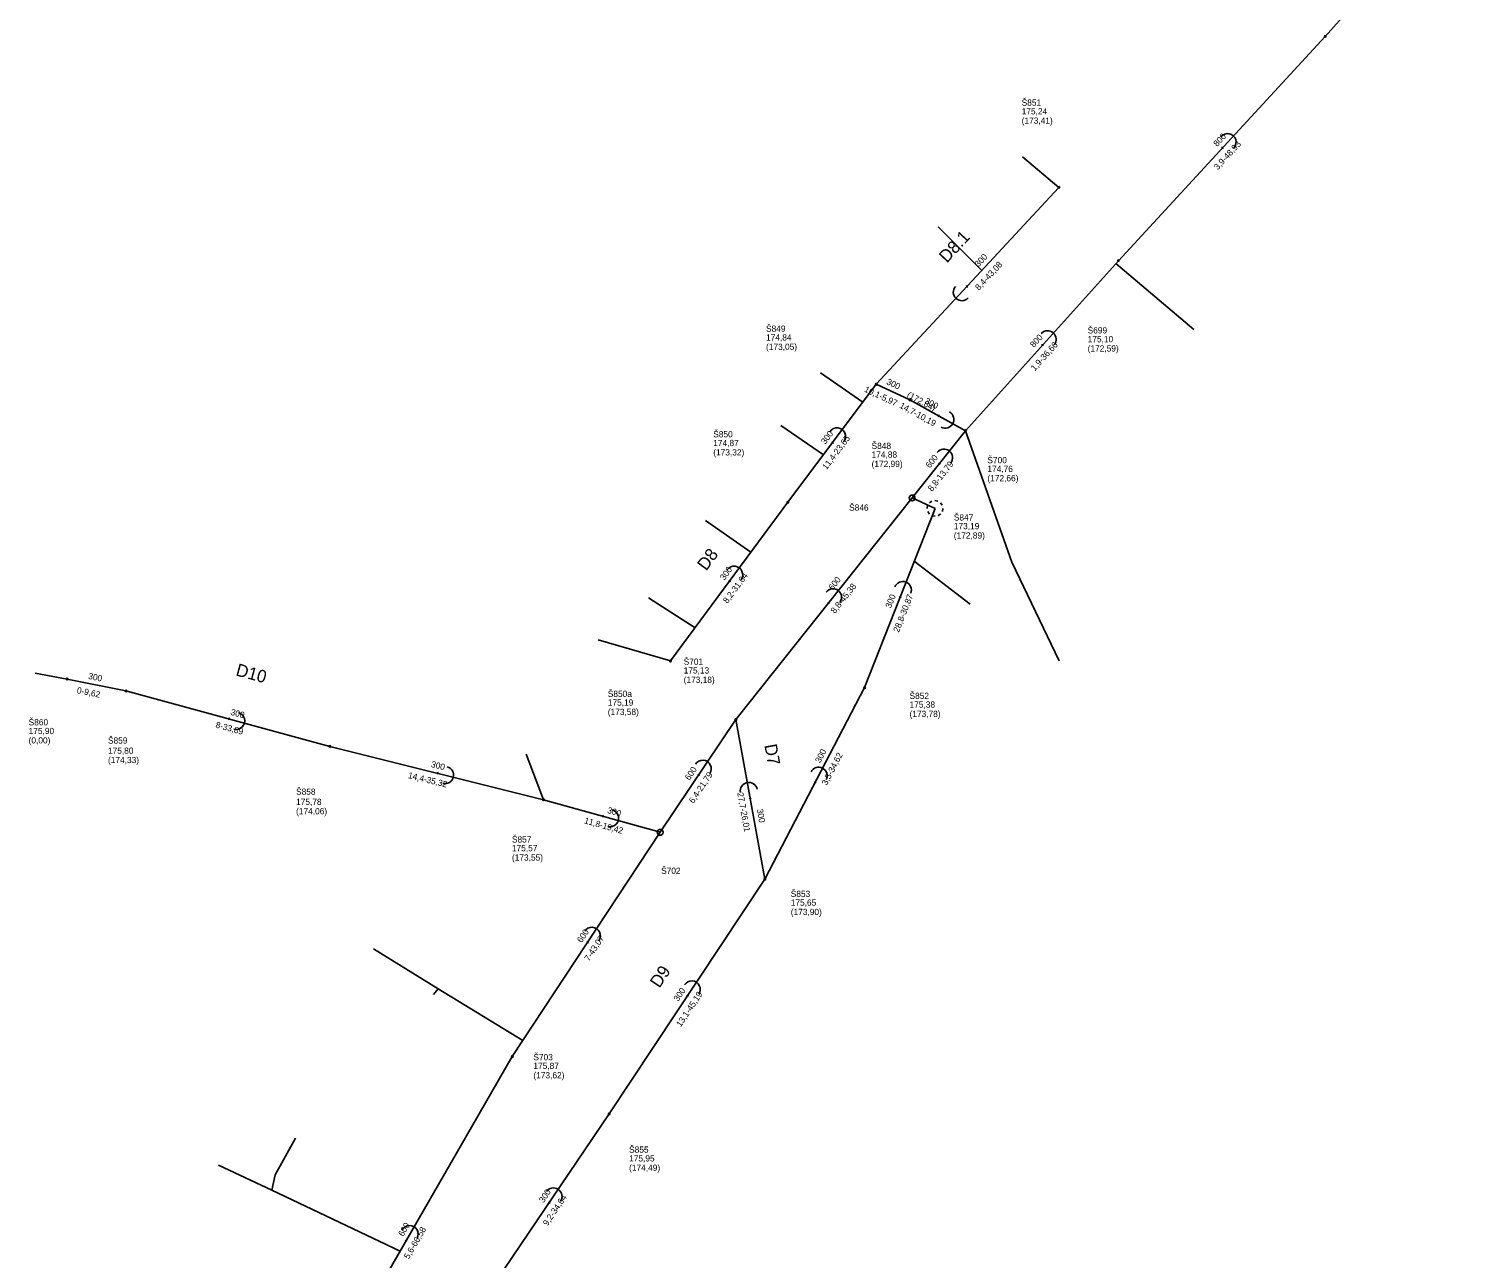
# Model space of a CAD drawing. Extents: x -548529 to -543591, y -1201432 to -1192608.
# Drawn here: x -545629 to -545396.5, y -1194134.3 to -1193937.1 of the extents above; entities that cross this region are included whole.
import ezdxf

# ---------------------------------------------------------------- set-up
doc = ezdxf.new("R2010")
doc.units = 0
for name, color, linetype in [('C3D_Bod-Značky', 7, 'Continuous'), ('C3D_Koridor', 7, 'Continuous'), ('C3D_Křižovatka', 7, 'Continuous'), ('C3D_Netisknutelná', 7, 'Continuous'), ('C3D_PP-zobrazeni v PR', 7, 'Continuous'), ('C3D_PR-Popisek', 7, 'Continuous'), ('C3D_SPR-Popisek', 7, 'Continuous'), ('C3D_Tlakove_potrubi_Popis', 7, 'Continuous'), ('C3D_ZPR-Formaty', 7, 'Continuous')]:
    doc.layers.add(name, color=color, linetype=linetype)

# ---------------------------------------------------------------- blocks, each defined once
blk = doc.blocks.new('100')
at = {"layer": 'Defpoints'}
blk.add_circle((0, 0), 0.127, dxfattribs=at)
blk = doc.blocks.new('101')
at = {"layer": 'Defpoints'}
blk.add_circle((0, 0), 0.463, dxfattribs=at)
blk = doc.blocks.new('102')
at = {"layer": 'Defpoints'}
for p, q in [((-1.17, -0.49), (-1.27, 0)), ((-1.17, 0.49), (-0.9, 0.9)), ((-0.49, 1.17), (0, 1.27)), ((0.49, 1.17), (0.9, 0.9)), ((1.17, 0.49), (1.27, 0)), ((-0.49, -1.17), (-0.9, -0.9)), ((0.49, -1.17), (0, -1.27)), ((1.17, -0.49), (0.9, -0.9))]:
    blk.add_line(p, q, dxfattribs=at)
blk = doc.blocks.new('86')
at = {"layer": 'Defpoints'}
blk.add_lwpolyline([(0.08, 0.14), (0.19, 0), (0.08, -0.14)], dxfattribs=at)
blk.add_arc((1.37, 0), 1.37, 270, 90, dxfattribs=at)
blk = doc.blocks.new('91')
at = {"layer": 'Defpoints'}
blk.add_lwpolyline([(0.08, 0.14), (0.19, 0), (0.08, -0.14)], dxfattribs=at)
blk.add_arc((1.37, 0), 1.37, 270, 90, dxfattribs=at)

msp = doc.modelspace()

# ---------------------------------------------------------------- linework, layer by layer
at = {"layer": 'C3D_Bod-Značky'}
for points in [[(-545421.142, -1193938.256), (-545396.484, -1193910.624)], [(-545454.318, -1193974.219), (-545421.142, -1193938.256)], [(-545463.86, -1193962.46), (-545493.163, -1193994.034)], [(-545478.832, -1194001.476), (-545454.318, -1193974.219)], [(-545507.34, -1194012.96), (-545493.163, -1193994.034)], [(-545493.163, -1193994.034), (-545487.754, -1193996.557)], [(-545487.754, -1193996.557), (-545478.832, -1194001.476)], [(-545487.415, -1194012.27), (-545478.832, -1194001.476)], [(-545526.15, -1194038.4), (-545507.34, -1194012.96)], [(-545515.662, -1194047.793), (-545487.415, -1194012.27)], [(-545495.027, -1194042.672), (-545483.733, -1194013.942)], [(-545483.733, -1194013.942), (-545487.415, -1194012.27)], [(-545622.922, -1194041.307), (-545613.493, -1194043.214)], [(-545613.493, -1194043.214), (-545580.788, -1194052.09)], [(-545511.007, -1194073.384), (-545495.027, -1194042.672)], [(-545527.812, -1194065.877), (-545515.662, -1194047.793)], [(-545511.007, -1194073.384), (-545515.662, -1194047.793)], [(-545580.788, -1194052.09), (-545546.515, -1194060.642)], [(-545546.515, -1194060.642), (-545527.812, -1194065.877)], [(-545551.526, -1194101.831), (-545527.812, -1194065.877)], [(-545535.994, -1194111.041), (-545511.007, -1194073.384)], [(-545584.807, -1194159.503), (-545569.894, -1194133.66), (-545551.526, -1194101.831)], [(-545555.391, -1194139.74), (-545535.994, -1194111.041)]]:
    msp.add_lwpolyline(points, dxfattribs=at)
at = {"layer": 'C3D_Koridor'}
for points in [[(-545463.86, -1193962.46), (-545469.711, -1193957.58)], [(-545476.245, -1193975.805), (-545483.202, -1193968.8)], [(-545454.706, -1193974.65), (-545442.238, -1193985.272)], [(-545495.305, -1193996.893), (-545502.079, -1193992.182)], [(-545501.629, -1194005.336), (-545508.485, -1194000.645)], [(-545478.832, -1194001.476), (-545471.428, -1194022.539), (-545463.838, -1194038.386)], [(-545513.272, -1194020.983), (-545520.525, -1194015.877)], [(-545487.048, -1194022.374), (-545478.091, -1194029.296)], [(-545522.208, -1194033.069), (-545529.702, -1194028.278)], [(-545526.15, -1194038.4), (-545537.781, -1194035.009)], [(-545622.922, -1194041.307), (-545628.047, -1194040.355)], [(-545546.515, -1194060.642), (-545549.299, -1194053.365)], [(-545549.841, -1194099.277), (-545563.417, -1194090.957), (-545573.785, -1194084.563)], [(-545563.417, -1194090.957), (-545564.157, -1194091.896)], [(-545590.088, -1194123.245), (-545589.572, -1194120.8), (-545586.282, -1194114.925)], [(-545569.529, -1194133.028), (-545590.088, -1194123.245), (-545598.657, -1194119.235)]]:
    msp.add_lwpolyline(points, dxfattribs=at)

# ---------------------------------------------------------------- block references
at = {"layer": 'C3D_PP-zobrazeni v PR'}
for name, p, xscale, yscale, rotation in [('100', (-545421.142, -1193938.256), 1.0000000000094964, 1.0000000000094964, -132.0000013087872), ('100', (-545463.86, -1193962.46), 1.0000000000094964, 1.0000000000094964, 47.99999869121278), ('100', (-545454.318, -1193974.219), 1.0000000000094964, 1.0000000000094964, -132.0000013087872), ('100', (-545493.163, -1193994.034), 1.000000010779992, 1.0000000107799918, -128.99999891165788), ('100', (-545487.754, -1193996.557), 1.0138865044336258, 1.0138865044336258, 152.43468640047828), ('100', (-545478.832, -1194001.476), 0.9999999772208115, 0.9999999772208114, 100.00000028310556), ('101', (-545487.415, -1194012.27), 1.000000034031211, 1.0000000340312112, -128.00000040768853), ('100', (-545507.34, -1194012.96), 1.000000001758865, 1.000000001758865, -125.99999933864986), ('102', (-545483.733, -1194013.942), 1.0000000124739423, 1.000000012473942, -67.0000004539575), ('100', (-545526.15, -1194038.4), 1.000000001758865, 1.000000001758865, -125.99999933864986), ('100', (-545622.922, -1194041.307), 1.0060666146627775, 1.0060666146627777, 167.3452647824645), ('100', (-545613.493, -1194043.214), 1.0028916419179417, 1.0028916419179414, 166.30279126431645), ('100', (-545495.027, -1194042.672), 0.9999999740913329, 0.9999999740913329, 65.99999939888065), ('100', (-545515.662, -1194047.793), 1.0000000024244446, 1.0000000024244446, 75.99999967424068), ('100', (-545580.788, -1194052.09), 1.0009848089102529, 1.000984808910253, 165.77567372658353), ('100', (-545546.515, -1194060.642), 1.0009848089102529, 1.000984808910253, 165.77567372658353), ('101', (-545527.812, -1194065.877), 1.0275072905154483, 1.027507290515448, -155.31089431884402), ('100', (-545511.007, -1194073.384), 0.9999999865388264, 0.9999999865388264, 59.99999955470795), ('100', (-545551.526, -1194101.831), 1.0000000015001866, 1.0000000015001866, -120.99999982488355), ('100', (-545535.994, -1194111.041), 0.9999999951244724, 0.9999999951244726, 56.999998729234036)]:
    msp.add_blockref(name, p, dxfattribs=dict(at, xscale=xscale, yscale=yscale, rotation=rotation))
at = {"layer": 'C3D_SPR-Popisek'}
for name, p, xscale, yscale, rotation in [('91', (-545437.73, -1193956.238), 1.0000000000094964, 1.0000000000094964, 47.99999869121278), ('91', (-545478.512, -1193978.247), 1.0000000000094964, 1.0000000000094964, -132.0000013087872), ('91', (-545466.575, -1193987.848), 1.0000000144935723, 1.0000000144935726, 49.00000089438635), ('91', (-545483.293, -1193999.016), 1.0072562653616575, 1.0072562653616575, -28.76666512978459), ('91', (-545500.252, -1194003.497), 1.000000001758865, 1.000000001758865, 54.00000066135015), ('91', (-545483.124, -1194006.873), 1.000000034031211, 1.0000000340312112, 51.999999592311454), ('91', (-545516.745, -1194025.68), 1.000000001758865, 1.000000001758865, 54.00000066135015), ('86', (-545489.38, -1194028.307), 0.9999999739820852, 0.9999999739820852, 68.99999941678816), ('91', (-545500.936, -1194029.274), 1.000000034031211, 1.0000000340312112, 51.999999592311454), ('86', (-545597.14, -1194047.652), 0.999999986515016, 0.9999999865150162, -15.000000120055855), ('86', (-545563.651, -1194056.366), 1.0009848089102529, 1.000984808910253, -14.224326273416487), ('91', (-545521.737, -1194056.835), 0.9999999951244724, 0.9999999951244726, 56.999998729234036), ('86', (-545503.017, -1194058.028), 0.9999999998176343, 0.9999999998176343, 63.00000066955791), ('86', (-545513.334, -1194060.588), 0.999999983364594, 0.9999999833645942, 101.0000002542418), ('86', (-545537.163, -1194063.26), 0.999999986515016, 0.9999999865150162, -15.000000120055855), ('91', (-545539.516, -1194083.622), 0.9999999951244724, 0.9999999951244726, 56.999998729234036), ('86', (-545523.5, -1194092.212), 0.9999999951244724, 0.9999999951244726, 56.999998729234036), ('86', (-545545.692, -1194125.39), 0.9999999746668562, 0.999999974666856, 55.999999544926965), ('91', (-545568.647, -1194131.5), 1.0000000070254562, 1.0000000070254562, 61.000001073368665)]:
    msp.add_blockref(name, p, dxfattribs=dict(at, xscale=xscale, yscale=yscale, rotation=rotation))

# ---------------------------------------------------------------- texts
at = {"layer": 'C3D_Křižovatka'}
for s, p in [('Š851', (-545469.83, -1193949.37)), ('Š849', (-545510.833, -1193985.624)), ('Š699', (-545459.248, -1193985.889)), ('Š850', (-545519.3, -1194002.55)), ('Š848', (-545493.904, -1194004.407)), ('Š700', (-545475.332, -1194006.696)), ('Š846', (-545497.505, -1194014.31)), ('Š847', (-545480.713, -1194015.882)), ('Š701', (-545524.042, -1194039.013)), ('Š850a', (-545536.21, -1194044.17)), ('Š852', (-545487.817, -1194044.492)), ('Š860', (-545629.102, -1194048.727)), ('Š859', (-545616.373, -1194051.654)), ('Š858', (-545586.208, -1194059.86)), ('Š857', (-545551.585, -1194067.512)), ('Š702', (-545527.662, -1194072.537)), ('Š853', (-545506.867, -1194076.244)), ('Š703', (-545548.146, -1194102.431)), ('Š855', (-545532.794, -1194117.251))]:
    msp.add_text(s, height=1, dxfattribs=at).set_placement(p)
at = {"layer": 'C3D_Netisknutelná'}
for s, rotation, p in [('D8.1', 47.14, (-545481.823, -1193974.686)), ('D8', 53.52, (-545520.426, -1194024.058)), ('D10', 344.82, (-545595.991, -1194040.702)), ('D7', 280.31, (-545511.11, -1194051.897)), ('D9', 56.43, (-545527.932, -1194090.961))]:
    msp.add_text(s, height=2, rotation=rotation, dxfattribs=at).set_placement(p)
at = {"layer": 'C3D_PR-Popisek'}
for s, rotation, p in [('800', 47.31, (-545438.47, -1193956.004)), ('300', 47.14, (-545476.744, -1193975.311)), ('800', 48.03, (-545467.859, -1193988.235)), ('300', 334.99, (-545491.617, -1193993.987)), ('300', 331.13, (-545485.51, -1193996.993)), ('300', 53.16, (-545501.315, -1194003.75)), ('600', 51.51, (-545484.566, -1194007.564)), ('300', 53.52, (-545517.514, -1194025.544)), ('600', 51.51, (-545500.135, -1194027.144)), ('300', 68.54, (-545490.81, -1194030.022)), ('300', 348.57, (-545619.599, -1194041.265)), ('300', 344.82, (-545596.788, -1194047.025)), ('300', 62.51, (-545502.143, -1194054.839)), ('300', 345.99, (-545564.636, -1194055.394)), ('600', 56.11, (-545523.113, -1194057.634)), ('300', 344.36, (-545536.369, -1194062.76)), ('300', 280.31, (-545512.331, -1194062.205)), ('600', 56.59, (-545540.4, -1194083.683)), ('300', 56.43, (-545524.923, -1194093.082)), ('300', 55.95, (-545546.522, -1194125.374)), ('600', 60.01, (-545569.026, -1194130.76))]:
    msp.add_text(s, height=1, rotation=rotation, dxfattribs=at).set_placement(p)
at = {"layer": 'C3D_Tlakove_potrubi_Popis'}
for s, p in [('(173,41)', (-545469.83, -1193952.27)), ('175,24 ', (-545469.83, -1193950.77)), ('174,84 ', (-545510.833, -1193987.024)), ('(173,05)', (-545510.833, -1193988.524)), ('(172,59)', (-545459.248, -1193988.789)), ('175,10 ', (-545459.248, -1193987.289)), ('(173,32)', (-545519.3, -1194005.45)), ('174,87 ', (-545519.3, -1194003.95)), ('174,88 ', (-545493.904, -1194005.807)), ('(172,99)', (-545493.904, -1194007.307)), ('174,76 ', (-545475.332, -1194008.096)), ('(172,66)', (-545475.332, -1194009.596)), ('173,19 ', (-545480.713, -1194017.282)), ('(172,89)', (-545480.713, -1194018.782)), ('175,13 ', (-545524.042, -1194040.413)), ('(173,18)', (-545524.042, -1194041.913)), ('(173,58)', (-545536.21, -1194047.07)), ('175,19 ', (-545536.21, -1194045.57)), ('(173,78)', (-545487.817, -1194047.392)), ('175,38 ', (-545487.817, -1194045.892)), ('(0,00)', (-545629.102, -1194051.627)), ('175,90 ', (-545629.102, -1194050.127)), ('175,80 ', (-545616.373, -1194053.284)), ('(174,33)', (-545616.373, -1194054.784)), ('175,78 ', (-545586.208, -1194061.49)), ('(174,06)', (-545586.208, -1194062.99)), ('(173,55)', (-545551.585, -1194070.412)), ('175,57 ', (-545551.585, -1194068.912)), ('175,65 ', (-545506.867, -1194077.644)), ('(173,90)', (-545506.867, -1194079.144)), ('(173,62)', (-545548.146, -1194105.331)), ('175,87 ', (-545548.146, -1194103.831)), ('175,95 ', (-545532.794, -1194118.651)), ('(174,49)', (-545532.794, -1194120.151))]:
    msp.add_text(s, height=1, dxfattribs=at).set_placement(p)
at = {"layer": 'C3D_ZPR-Formaty'}
for s, rotation, p in [('3,9-48,93', 47.31, (-545438.392, -1193959.748)), ('8,4-43,08', 47.14, (-545476.674, -1193979.062)), ('1,9-36,66', 48.03, (-545467.734, -1193991.979)), ('10,1-5,97', 334.99, (-545495.166, -1193995.194)), ('  (172,84)   ', 331.13, (-545488.981, -1193995.652)), ('14,7-10,19', 331.13, (-545489.524, -1193997.748)), ('11,4-23,65', 53.16, (-545501.124, -1194007.83)), ('8,8-13,79', 51.51, (-545484.21, -1194011.299)), ('8,2-31,64', 53.52, (-545517.034, -1194029.267)), ('8,8-45,38', 51.51, (-545499.779, -1194030.879)), ('28,8-30,87', 68.54, (-545489.54, -1194033.906)), ('0-9,62', 348.57, (-545621.439, -1194043.55)), ('8-33,89', 344.82, (-545599.201, -1194049.065)), ('3,5-34,62', 62.51, (-545501.087, -1194058.431)), ('14,4-35,32', 345.99, (-545568.322, -1194057.16)), ('6,4-21,79', 56.11, (-545522.466, -1194061.326)), ('27,7-26,01', 280.31, (-545515.452, -1194059.576)), ('11,8-19,42', 344.36, (-545540.07, -1194064.419)), ('7-43,07', 56.59, (-545539.223, -1194086.626)), ('13,1-45,19', 56.43, (-545524.498, -1194097.151)), ('9,2-34,64', 55.95, (-545545.883, -1194129.065)), ('5,6-66,58', 60.01, (-545568.123, -1194134.399))]:
    msp.add_text(s, height=1, rotation=rotation, dxfattribs=at).set_placement(p)

doc.saveas('drawing.dxf')
